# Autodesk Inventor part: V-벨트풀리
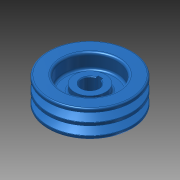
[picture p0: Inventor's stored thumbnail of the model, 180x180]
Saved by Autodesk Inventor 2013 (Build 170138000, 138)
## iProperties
Created: 2021-06
Part Number: V-벨트풀리
Material: 알루미늄 6061
Document SubType Name: Modeling
Designer: mdu
Density: 1 g/cm^3
CustomPartVersion: 1
Author: mdu
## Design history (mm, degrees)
sketch "주 스케치"
  geometry: L1 (0, 35)-(54.5, 35); L2 (54.5, 35)-(54.5, 15.55); L3 (54.5, 15.55)-(42, 11.488); L4 (42, 11.488)-(42, 8.512); L5 (42, 8.512)-(54.5, 4.45); L6 (54.5, 4.45)-(54.5, 0); L7 (54.5, 0)-(0, 0); L8 (50.5, 14.25)-(50.5, 5.75); L9 (42, 10)-(50.5, 10); L10 (54.5, 15.55)-(54.5, 4.45); L11 (0, -4)-(0, 24) reference; L12 (0, 0)-(0, 35)
  constraints: 22 end point, 5 perpendicular, 2 collinear, 2 midpoint, 2 point on line, 1 parallel
  dimensions: "d0" = 8.5 distance of L8.start L8.end (= da_Bw); "d1" = 36 deg angle of L3 L5 (= da_Alfa); "d2" = 4 distance between parallel lines of L2 L8 (= da_c); "d6" = 35 distance between parallel lines of L7 L1 (computed from d5, da_ng, da_Sg); "d21" = 101 diameter of L8 L11 (= da_Dw); "d25" = 12.5 distance between parallel lines of L4 L10 (= da_Hd); "d27" = 10 distance between parallel lines of L7 L9 (= da_Se)
node "평 벨트"
revolve "본체" stored, may be unused: angle "d7" = 90 deg
revolve "그루브" stored, may be unused: angle "d15" = 90 deg
fillet "외부 모깎기" dims "d8" = 0.5 (= da_r1), "d10" = 0, "da_r1" = 0.5 [user parameter; used in 1 equation term]
fillet "내부 모깎기" dims "d9" = 1 (= da_r2), "d11" = 0, "da_r2" = 1 [user parameter; used in 1 equation term]
sketch "스케치2"
  geometry: L1 (0, 0)-(0, 35); L2 (-54.5, 35)-(54.5, 35) reference; L3 (0, 35)-(35, 35); L4 (35, 35)-(35, 16); L5 (35, 16)-(20, 16); L6 (20, 16)-(20, 25); L7 (20, 25)-(0, 25); L8 (35, 0)-(35, 6); L9 (35, 6)-(20, 6); L10 (20, 6)-(20, 0); L11 (20, 0)-(35, 0); L12 (-54.5, 0)-(54.5, 0) reference
  constraints: 20 end point, 5 perpendicular, 3 parallel, 2 point on line, 2 vertical alignment, 1 collinear, 1 midpoint, 1 vertical
  dimensions: "d28" = 9 distance between parallel lines of L7 L5; "d30" = 6 distance of L9.end L10.end; "d31" = 10 distance between parallel lines of L9 L5; "d32" = 40 diameter of L10 L1; "d33" = 70 diameter of L8 L1
revolve "회전3" sketch "스케치2" stored, may be unused: angle "d34" = 90 deg
fillet "모깎기3" dims "d35" = 2, "d36" = 3
node "키홈1"
chamfer "모따기1" distance "d37" = 1; stored, may be unused: second distance "d38" = 2, angle "d39" = 45 deg
body "Solid1"
pattern_linear "그루브 패턴" dims "d18" = 15 (= da_Sg)
feature "허브 키홈"
other parameters: "da_Bw" = 8.5 [user parameter; used in 1 equation term], "da_Alfa" = 36 deg [user parameter; used in 1 equation term], "da_c" = 4 [user parameter; used in 1 equation term], "da_Dw" = 101 [user parameter; used in 1 equation term], "da_Hd" = 12.5 [user parameter; used in 1 equation term], "da_Se" = 10 [user parameter; used in 2 equation terms], "da_Sg" = 15 [user parameter; used in 2 equation terms], "d24" = 0, "d26" = 0
